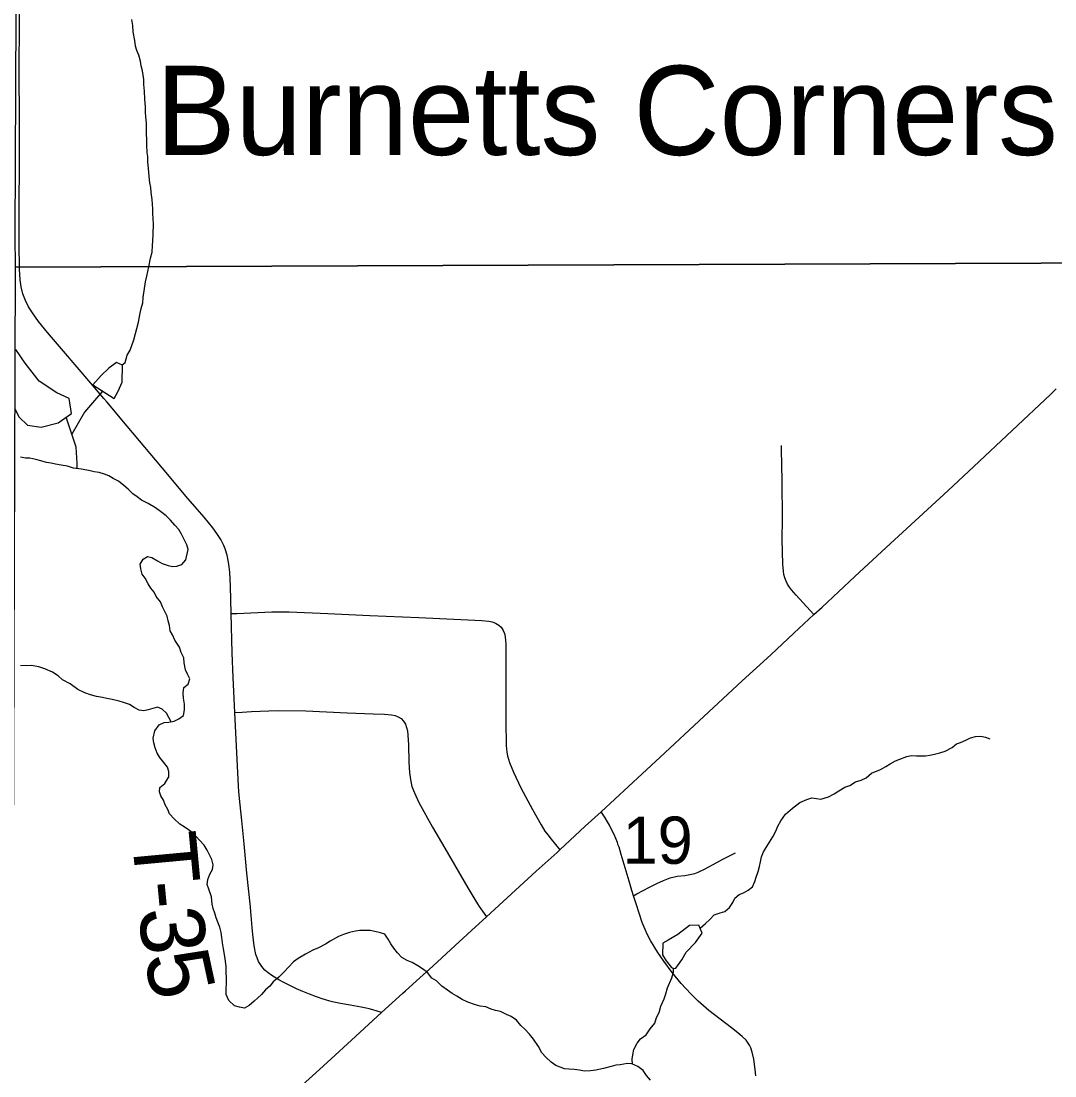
# Model space of a CAD drawing. Extents: x 0 to 34, y 0 to 22.
# Drawn here: x 5.655 to 6.57, y 18.155 to 19.089 of the extents above; entities that cross this region are included whole.
import ezdxf

# ---------------------------------------------------------------- set-up
doc = ezdxf.new("R2010")
doc.units = 0
for name, color, linetype in [('GM_X_Minor_Lake', 7, 'Continuous'), ('GM_X_Minor_River', 7, 'Continuous'), ('GM_X_Section', 7, 'Continuous'), ('GM_X_Section_Text', 7, 'Continuous'), ('GM_X_State_Route', 7, 'Continuous'), ('GM_X_Township_Road', 7, 'Continuous'), ('GM_X_Township_Road_Text', 7, 'Continuous'), ('GM_X_Unincorporated_Text', 7, 'Continuous')]:
    doc.layers.add(name, color=color, linetype=linetype)

msp = doc.modelspace()

# ---------------------------------------------------------------- linework, layer by layer
at = {"layer": 'GM_X_Minor_Lake'}
for points in [[(5.64904, 18.7459), (5.65326, 18.73796), (5.6605, 18.73081), (5.67264, 18.72901), (5.68776, 18.73292), (5.69944, 18.74135), (5.69745, 18.75461), (5.68644, 18.75945), (5.67084, 18.76996), (5.65861, 18.78579), (5.65019, 18.79786)], [(5.73722, 18.75453), (5.74096, 18.761), (5.74432, 18.76899), (5.74459, 18.78417), (5.73927, 18.7864), (5.73249, 18.78142), (5.72572, 18.77492), (5.71858, 18.76652)], [(5.71858, 18.76652), (5.73722, 18.75453)], [(6.23456, 18.2501), (6.23982, 18.25735), (6.24356, 18.2642), (6.25183, 18.27261), (6.25783, 18.281), (6.25475, 18.28818), (6.24642, 18.28773), (6.23625, 18.27969), (6.22758, 18.2747), (6.22305, 18.27201), (6.22274, 18.26177), (6.22581, 18.25648)], [(6.22581, 18.25648), (6.23064, 18.25071), (6.23266, 18.2497), (6.23456, 18.2501)]]:
    msp.add_lwpolyline(points, dxfattribs=at)
at = {"layer": 'GM_X_Minor_River'}
for points in [[(5.74433, 18.78427), (5.74701, 18.78653), (5.74883, 18.79301), (5.75144, 18.79722), (5.75474, 18.80639), (5.75872, 18.82201), (5.76016, 18.82849), (5.76123, 18.8342), (5.76268, 18.83916), (5.763, 18.8441), (5.7651, 18.8578), (5.76618, 18.86276), (5.76797, 18.87114), (5.76939, 18.87875), (5.77085, 18.88409), (5.77115, 18.89017), (5.77148, 18.89398), (5.77178, 18.90006), (5.77204, 18.90918), (5.77199, 18.91336), (5.77154, 18.91867), (5.77149, 18.92246), (5.771, 18.93082), (5.77016, 18.93688), (5.76972, 18.94143), (5.76891, 18.9456), (5.76845, 18.95129), (5.7676, 18.9585), (5.76715, 18.96381), (5.76708, 18.96875), (5.76665, 18.97254), (5.76619, 18.979), (5.76599, 18.99381), (5.76594, 18.99836), (5.76548, 19.00406), (5.76505, 19.00823), (5.76499, 19.01278), (5.76452, 19.01962), (5.76404, 19.02683), (5.76359, 19.03252), (5.76353, 19.03708), (5.76229, 19.04466), (5.76109, 19.0492), (5.76066, 19.05337), (5.75907, 19.05867), (5.75749, 19.06283), (5.7563, 19.06661), (5.75548, 19.07154), (5.75424, 19.07912), (5.75378, 19.08481), (5.75295, 19.09012)], [(5.72699, 18.76111), (5.71117, 18.74257), (5.69984, 18.72308)], [(5.70445, 18.6924), (5.70467, 18.6974), (5.70381, 18.71142), (5.69477, 18.73797)], [(5.77056, 18.61363), (5.77554, 18.61065), (5.77976, 18.60843), (5.7851, 18.6066), (5.78892, 18.60589), (5.79272, 18.60594), (5.79726, 18.60752), (5.80063, 18.61175), (5.80279, 18.62089), (5.8016, 18.62505), (5.79926, 18.62958), (5.79691, 18.63449), (5.79457, 18.63864), (5.7911, 18.64239), (5.78724, 18.64689), (5.78339, 18.65064), (5.7784, 18.65437), (5.77379, 18.65773), (5.76728, 18.66144), (5.76153, 18.66441), (5.75769, 18.66739), (5.75385, 18.67), (5.74962, 18.67412), (5.74577, 18.67749), (5.74116, 18.68123), (5.73656, 18.68382), (5.73273, 18.68605), (5.72891, 18.68752), (5.72394, 18.68897), (5.71975, 18.68968), (5.71594, 18.69039), (5.70831, 18.6918), (5.70145, 18.69285), (5.6961, 18.69468), (5.69039, 18.69536), (5.68543, 18.69644), (5.68162, 18.69715), (5.67743, 18.69785), (5.67246, 18.6993), (5.66789, 18.70038), (5.66254, 18.70183), (5.65874, 18.70178), (5.65455, 18.70248)], [(5.89616, 18.25557), (5.89166, 18.25096), (5.88753, 18.24634), (5.88302, 18.2421), (5.87814, 18.23786), (5.87514, 18.23402), (5.87138, 18.23093), (5.86763, 18.2267), (5.86124, 18.22092), (5.85673, 18.21706), (5.85257, 18.21473), (5.84838, 18.21543), (5.8438, 18.21651), (5.8388, 18.22138), (5.83645, 18.22667), (5.83638, 18.23198), (5.8367, 18.23617), (5.8365, 18.25174), (5.83524, 18.26046), (5.83401, 18.26728), (5.83319, 18.27259), (5.83274, 18.27714), (5.83193, 18.28169), (5.83073, 18.28623), (5.82915, 18.29077), (5.82757, 18.29454), (5.82638, 18.29871), (5.82481, 18.30286), (5.82399, 18.30665), (5.82353, 18.3131), (5.82116, 18.31991), (5.81958, 18.32407), (5.82029, 18.32863), (5.82213, 18.33321), (5.82435, 18.33743), (5.82506, 18.34161), (5.82386, 18.34615), (5.81957, 18.35445), (5.81685, 18.35898), (5.81299, 18.36348), (5.80721, 18.36948), (5.80298, 18.37246), (5.79915, 18.37507), (5.79531, 18.37768), (5.79031, 18.38217), (5.78644, 18.38668), (5.78487, 18.39046), (5.78254, 18.39461), (5.78096, 18.39876), (5.77863, 18.40253), (5.77744, 18.40631), (5.77777, 18.41011), (5.78229, 18.41359), (5.78564, 18.41934), (5.78557, 18.42428), (5.78439, 18.42806), (5.78129, 18.43219), (5.77781, 18.43671), (5.77548, 18.44047), (5.77351, 18.44501), (5.77231, 18.44955), (5.77188, 18.45372), (5.77332, 18.4602), (5.77705, 18.46557), (5.78159, 18.46753), (5.78577, 18.46796), (5.79032, 18.46878), (5.79448, 18.47074), (5.79862, 18.47383), (5.7997, 18.47878), (5.79963, 18.48372), (5.7988, 18.48903), (5.79836, 18.49358), (5.79906, 18.49853), (5.80282, 18.50162), (5.80428, 18.50619), (5.80233, 18.51035), (5.80038, 18.51412), (5.79915, 18.52056), (5.7991, 18.52474), (5.79675, 18.52964), (5.79517, 18.53418), (5.79091, 18.54058), (5.78895, 18.54512), (5.787, 18.54889), (5.78617, 18.55343), (5.78498, 18.5576), (5.78417, 18.56177), (5.78025, 18.57007), (5.77829, 18.5746), (5.77443, 18.57911), (5.77286, 18.58289), (5.76977, 18.58664), (5.76744, 18.59041), (5.76471, 18.59531), (5.762, 18.59907), (5.7608, 18.60362), (5.76037, 18.60779), (5.76297, 18.61238), (5.76674, 18.61471), (5.77056, 18.61363)], [(5.78774, 18.46832), (5.78376, 18.47591), (5.77991, 18.47928), (5.77571, 18.48112), (5.76737, 18.47873), (5.76358, 18.47792), (5.75939, 18.47863), (5.75517, 18.48085), (5.75096, 18.48345), (5.74561, 18.48528), (5.74179, 18.48637), (5.73569, 18.48781), (5.73073, 18.48888), (5.72692, 18.48959), (5.72158, 18.49065), (5.71624, 18.4921), (5.71127, 18.49394), (5.70514, 18.49689), (5.69824, 18.50174), (5.69172, 18.50545), (5.68787, 18.50882), (5.68289, 18.51217), (5.676, 18.51512), (5.67065, 18.51694), (5.66379, 18.51799), (5.65429, 18.51786)], [(6.25597, 18.28533), (6.26082, 18.2897), (6.26458, 18.29316), (6.26833, 18.29739), (6.27363, 18.29898), (6.2778, 18.30018), (6.28194, 18.30365), (6.28492, 18.30825), (6.28677, 18.31207), (6.29053, 18.31516), (6.29432, 18.31673), (6.29847, 18.31907), (6.30223, 18.32216), (6.30446, 18.32674), (6.30555, 18.33056), (6.30738, 18.33552), (6.30846, 18.34009), (6.30955, 18.34429), (6.31026, 18.34847), (6.3121, 18.35306), (6.31508, 18.35765), (6.31731, 18.36148), (6.32029, 18.36646), (6.32289, 18.37143), (6.32474, 18.37564), (6.32734, 18.38061), (6.33144, 18.38636), (6.33784, 18.39177), (6.34424, 18.39679), (6.35029, 18.39953), (6.35484, 18.40073), (6.35902, 18.40041), (6.36284, 18.3997), (6.36966, 18.40169), (6.37457, 18.40441), (6.37871, 18.40713), (6.384, 18.41024), (6.38854, 18.41182), (6.39344, 18.41492), (6.39837, 18.41651), (6.4029, 18.41846), (6.40779, 18.42271), (6.41574, 18.42586), (6.42027, 18.42857), (6.42404, 18.4309), (6.42895, 18.43363), (6.43273, 18.4352), (6.43879, 18.43756), (6.44296, 18.43838), (6.44753, 18.43806), (6.45551, 18.43816), (6.45931, 18.43859), (6.46349, 18.43941), (6.46803, 18.44061), (6.47296, 18.44219), (6.479, 18.44531), (6.48276, 18.44878), (6.48655, 18.44997), (6.49108, 18.45193), (6.49524, 18.45389), (6.49979, 18.45509), (6.50435, 18.45553), (6.50855, 18.45445), (6.51237, 18.45298)], [(6.21204, 18.15077), (6.20857, 18.15491), (6.20547, 18.15942), (6.20086, 18.16278), (6.1955, 18.16537), (6.19169, 18.1657), (6.18524, 18.16447), (6.18145, 18.16404), (6.17728, 18.16285), (6.17045, 18.16124), (6.16363, 18.15962), (6.15907, 18.15918), (6.15375, 18.15873), (6.14917, 18.15981), (6.14461, 18.16013), (6.13966, 18.16044), (6.13585, 18.16077), (6.12821, 18.16371), (6.12398, 18.16669), (6.11936, 18.17119), (6.11589, 18.17494), (6.11277, 18.1806), (6.10851, 18.187), (6.10503, 18.19151), (6.10117, 18.19564), (6.09732, 18.19938), (6.09346, 18.20389), (6.08885, 18.20725), (6.08464, 18.20909), (6.07928, 18.21168), (6.07471, 18.21238), (6.07089, 18.21385), (6.0663, 18.21568), (6.06135, 18.21638), (6.05715, 18.21746), (6.05027, 18.22003), (6.0453, 18.22224), (6.04069, 18.22522), (6.03648, 18.22744), (6.03226, 18.23042), (6.02727, 18.23415), (6.02264, 18.23865), (6.01843, 18.24125), (6.01456, 18.24614), (6.01033, 18.2495), (6.00612, 18.25211), (6.00113, 18.25508), (5.99655, 18.25692), (5.99195, 18.25951), (5.98809, 18.26364), (5.98499, 18.26778), (5.98228, 18.27154), (5.97995, 18.27569), (5.97685, 18.2802), (5.97303, 18.28129), (5.96807, 18.28237), (5.96387, 18.28345), (5.95475, 18.28333), (5.95095, 18.2829), (5.94564, 18.28169), (5.94034, 18.27971), (5.9358, 18.27814), (5.92863, 18.27386), (5.92448, 18.27115), (5.91806, 18.26802), (5.91314, 18.26606), (5.90672, 18.26255), (5.9003, 18.25867), (5.89616, 18.25557)], [(6.19611, 18.16507), (6.19583, 18.16955), (6.19654, 18.17336), (6.19724, 18.17793), (6.20021, 18.18367), (6.2032, 18.1875), (6.2081, 18.19099), (6.21183, 18.19636), (6.21595, 18.20135), (6.21741, 18.20631), (6.21963, 18.21089), (6.22108, 18.21623), (6.22404, 18.22273), (6.2255, 18.22731), (6.22695, 18.23264), (6.23102, 18.24143), (6.23248, 18.24639), (6.23246, 18.2498)]]:
    msp.add_lwpolyline(points, dxfattribs=at)
at = {"layer": 'GM_X_Section'}
for points in [[(5.65424, 19.88127), (6.77985, 19.89133), (6.78469, 18.87524), (5.64995, 18.87081), (5.64978, 18.89848)], [(5.64995, 18.87081), (6.78469, 18.87524), (6.79787, 17.8558), (5.64653, 17.84104), (5.64681, 17.91722)]]:
    msp.add_lwpolyline(points, close=True, dxfattribs=at)
at = {"layer": 'GM_X_State_Route'}
for points in [[(5.99288, 18.22789), (5.99507, 18.22988), (6.00793, 18.24144), (6.01928, 18.25186), (6.03527, 18.26663), (6.05357, 18.28349), (6.06678, 18.29548), (6.07427, 18.30228), (6.11099, 18.33578), (6.1294, 18.35246), (6.1319, 18.3548), (6.15433, 18.37582), (6.16837, 18.3886), (6.20464, 18.42209), (6.22062, 18.43681), (6.25917, 18.47277), (6.29332, 18.50445), (6.31846, 18.52757), (6.33889, 18.54663), (6.35669, 18.5631), (6.36392, 18.56979), (6.39284, 18.59687), (6.42064, 18.62252), (6.47547, 18.6732), (6.49833, 18.69423), (6.56613, 18.75814), (6.5712, 18.76302)], [(5.64791, 17.96009), (5.65876, 17.96792), (5.69923, 17.99666), (5.74985, 18.03262), (5.82013, 18.08275), (5.85795, 18.11005), (5.8686, 18.1179), (5.87776, 18.12465), (5.88076, 18.127), (5.88399, 18.12952), (5.89749, 18.14078), (5.90122, 18.14413), (5.91595, 18.15733), (5.92934, 18.16966), (5.94734, 18.18629), (5.97398, 18.21062), (5.99288, 18.22789)]]:
    msp.add_lwpolyline(points, dxfattribs=at)
at = {"layer": 'GM_X_Township_Road'}
for points in [[(5.65506, 18.85333), (5.65421, 18.85958), (5.65371, 18.86457), (5.65362, 18.86896), (5.65328, 18.89194), (5.65311, 18.90396), (5.65321, 18.9188), (5.65364, 18.96845), (5.65351, 19.00259), (5.65332, 19.04294), (5.65345, 19.08951), (5.65354, 19.10336)], [(5.72824, 18.75453), (5.71673, 18.76812), (5.69236, 18.79633), (5.67825, 18.81293), (5.67039, 18.82263), (5.6649, 18.83026), (5.66162, 18.83563), (5.65879, 18.84127), (5.65758, 18.84419), (5.65656, 18.84719), (5.65506, 18.85333)], [(5.84076, 18.56406), (5.84025, 18.58843), (5.8397, 18.60058), (5.83925, 18.60544), (5.83856, 18.60964), (5.83733, 18.61568), (5.83555, 18.62152), (5.83439, 18.62433), (5.8316, 18.62975), (5.82825, 18.6349), (5.82464, 18.63994), (5.81689, 18.64957), (5.80879, 18.65887), (5.80077, 18.66817), (5.78479, 18.68715), (5.74883, 18.7301), (5.7308, 18.75151), (5.72824, 18.75453)], [(6.35669, 18.5631), (6.35338, 18.5667), (6.34088, 18.58031), (6.33689, 18.58501), (6.33507, 18.58749), (6.33345, 18.59011), (6.33205, 18.59286), (6.33094, 18.59573), (6.33014, 18.59871), (6.32964, 18.60175), (6.32916, 18.6079), (6.32858, 18.62954), (6.3288, 18.64803), (6.32855, 18.68164), (6.32808, 18.70932), (6.32813, 18.7128)], [(5.84076, 18.56406), (5.84581, 18.56426), (5.87678, 18.56551), (5.89229, 18.5655), (5.92638, 18.56402), (5.96356, 18.56226), (6.00696, 18.56047), (6.03176, 18.55949), (6.06273, 18.55799), (6.0689, 18.55737), (6.07191, 18.55666), (6.07498, 18.55557), (6.07778, 18.55376), (6.07975, 18.55195), (6.08172, 18.54915), (6.08279, 18.54643), (6.08337, 18.54338), (6.08372, 18.54031), (6.08387, 18.53721), (6.08397, 18.5186), (6.08387, 18.48451), (6.08385, 18.46901), (6.0843, 18.44732), (6.08492, 18.44117), (6.08551, 18.43814), (6.08726, 18.43224), (6.09076, 18.42364), (6.09736, 18.40964), (6.10753, 18.39045), (6.11513, 18.37694), (6.11864, 18.37145), (6.12116, 18.36809), (6.12414, 18.36412), (6.12788, 18.35946), (6.1319, 18.3548)], [(5.84415, 18.47653), (5.84267, 18.50757), (5.84176, 18.52933), (5.84076, 18.56406)], [(5.84415, 18.47653), (5.8505, 18.47688), (5.85896, 18.47733), (5.86652, 18.47766), (5.87433, 18.478), (5.88288, 18.47816), (5.90706, 18.47783), (5.94357, 18.47611), (5.96657, 18.47527), (5.97667, 18.47489), (5.98287, 18.47443), (5.9859, 18.47379), (5.9888, 18.47271), (5.99137, 18.47102), (5.99346, 18.46875), (5.99506, 18.46611), (5.99618, 18.46322), (5.99683, 18.46019), (5.99774, 18.44803), (5.99806, 18.43252), (5.99869, 18.42326), (5.99955, 18.4171), (6.00093, 18.41104), (6.00303, 18.40519), (6.00705, 18.39677), (6.01915, 18.375), (6.03015, 18.35617), (6.05041, 18.32116), (6.05659, 18.31076), (6.05895, 18.30709), (6.0605, 18.30466), (6.06338, 18.30046), (6.06678, 18.29548)], [(5.97398, 18.21062), (5.97007, 18.21189), (5.96621, 18.21315), (5.96313, 18.21388), (5.96035, 18.21455), (5.95583, 18.21537), (5.94607, 18.21712), (5.93753, 18.21873), (5.93185, 18.21994), (5.92821, 18.22088), (5.92444, 18.22186), (5.92129, 18.22291), (5.91833, 18.22389), (5.91638, 18.22459), (5.91017, 18.22707), (5.90433, 18.22931), (5.89865, 18.23176), (5.88736, 18.23739), (5.88308, 18.23969), (5.877, 18.24364), (5.87355, 18.24595), (5.8708, 18.2483), (5.86901, 18.25042), (5.86749, 18.25224), (5.86516, 18.25598), (5.86386, 18.25927), (5.8627, 18.26223), (5.86122, 18.26979), (5.86013, 18.27983), (5.85959, 18.28608), (5.85869, 18.29676), (5.85841, 18.29987), (5.85801, 18.30433), (5.85482, 18.33426), (5.85227, 18.36025), (5.85025, 18.3808), (5.84888, 18.39479), (5.84775, 18.40626), (5.84738, 18.4114), (5.84698, 18.41713), (5.84415, 18.47653)], [(6.19697, 18.31393), (6.19549, 18.31866), (6.19303, 18.32709), (6.18958, 18.33893), (6.18612, 18.35077), (6.18421, 18.35721), (6.18355, 18.35901), (6.18271, 18.36125), (6.17975, 18.3683), (6.1788, 18.37038), (6.17562, 18.37675), (6.17412, 18.37947), (6.17204, 18.38311), (6.17027, 18.38576), (6.16837, 18.3886)], [(6.19697, 18.31393), (6.20009, 18.31574), (6.21105, 18.32163), (6.21753, 18.32511), (6.22357, 18.32774), (6.22949, 18.32987), (6.23573, 18.33136), (6.24232, 18.33218), (6.24833, 18.3332), (6.25133, 18.33399), (6.25425, 18.335), (6.25988, 18.33755), (6.27072, 18.34362), (6.27603, 18.34664), (6.28129, 18.34927), (6.28722, 18.35223)], [(6.30531, 18.15456), (6.30482, 18.16015), (6.30351, 18.16953), (6.30203, 18.17561), (6.30071, 18.17939), (6.29956, 18.1817), (6.2966, 18.18614), (6.29331, 18.18959), (6.28937, 18.19288), (6.28379, 18.19711), (6.27357, 18.20471), (6.26374, 18.21254), (6.25434, 18.22075), (6.24765, 18.22731), (6.23925, 18.23654), (6.23135, 18.24618), (6.22392, 18.2562), (6.21867, 18.26393), (6.21219, 18.27458), (6.20951, 18.27952), (6.20733, 18.28416), (6.2047, 18.29058), (6.19927, 18.30702), (6.19697, 18.31393)]]:
    msp.add_lwpolyline(points, dxfattribs=at)

# ---------------------------------------------------------------- texts
at = {"layer": 'GM_X_Section_Text'}
msp.add_text('19', height=0.041856, rotation=0.00001, dxfattribs=at).set_placement((6.18721, 18.34242))
at = {"layer": 'GM_X_Township_Road_Text'}
for s, rotation, p in [('T', 275.33897, (5.75276, 18.3679)), ('-', 275.39125, (5.75672, 18.32553)), ('3', 275.64777, (5.75894, 18.30203)), ('5', 282.17554, (5.76348, 18.26023))]:
    msp.add_text(s, height=0.05682, rotation=rotation, dxfattribs=at).set_placement(p)
at = {"layer": 'GM_X_Unincorporated_Text'}
msp.add_text('Burnetts Corners', height=0.0789773, rotation=0.00001, dxfattribs=at).set_placement((5.7743, 18.97023))

doc.saveas('drawing.dxf')
